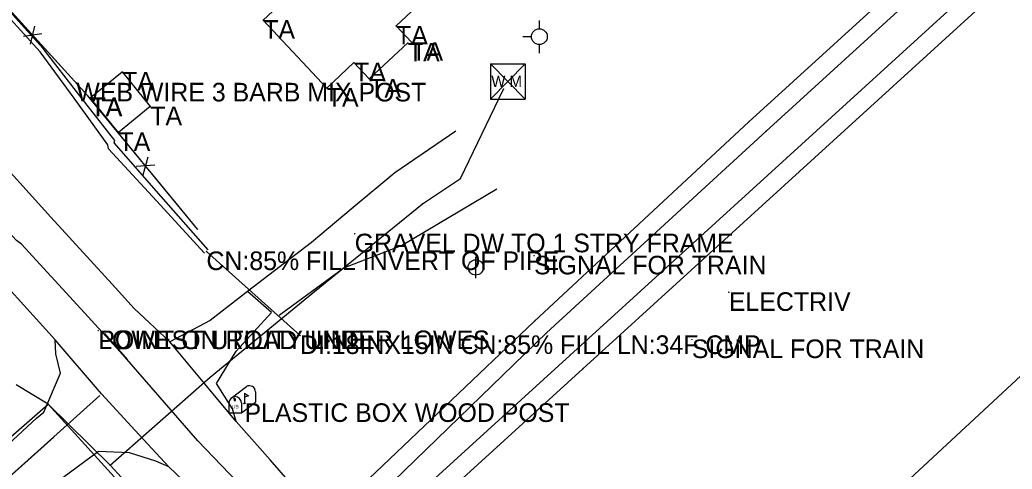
# Model space of a CAD drawing. Extents: x 1660112 to 1662239, y 668919 to 671377.
# Drawn here: x 1661444.9 to 1661711.4, y 670014.9 to 670135.7 of the extents above; entities that cross this region are included whole.
import ezdxf

# ---------------------------------------------------------------- set-up
doc = ezdxf.new("R2010")
doc.units = 0
for name, color, linetype in [('S_BUILDING', 7, 'Continuous'), ('S_BUILDING_ANNOT', 7, 'Continuous'), ('S_DITCHLINE', 7, 'Continuous'), ('S_DRG_PT_SYM', 7, 'Continuous'), ('S_DRIVEWAY', 7, 'Continuous'), ('S_EDGE_PAVEMENT', 7, 'Continuous'), ('S_ELECTRIC_UTILITIES_ANNOT', 7, 'Continuous'), ('S_FENCE', 7, 'Continuous'), ('S_FIBER_OPTIC_CABLE', 7, 'Continuous'), ('S_MAILBOX', 7, 'Continuous'), ('S_MAILBOX_ANNOT', 7, 'Continuous'), ('S_MISC_STRUCTURES_ANNOT', 7, 'Continuous'), ('S_MSC_PT_SYM', 7, 'Continuous'), ('S_PAVEMENT_CROWN', 7, 'Continuous'), ('S_RAILROAD', 7, 'Continuous'), ('S_SIDE_DRAIN', 7, 'Continuous'), ('S_SIDE_DRAIN_ANNOT', 7, 'Continuous'), ('S_STR_PT_SYM', 7, 'Continuous'), ('S_SURVEY_TEXT_ANNOT', 7, 'Continuous'), ('S_UTILITY_POLE', 7, 'Continuous'), ('S_UTL_PT_SYM', 7, 'Continuous'), ('S_WATER_UTILITIES', 7, 'Continuous')]:
    doc.layers.add(name, color=color, linetype=linetype)

msp = doc.modelspace()

# ---------------------------------------------------------------- linework, layer by layer
at = {"layer": 'S_BUILDING'}
for p, q in [((1661510.29, 670135.6), (1661528.55, 670152.68)), ((1661558.38, 670145.66), (1661545.97, 670134.05)), ((1661527.37, 670117.34), (1661510.29, 670135.6)), ((1661545.97, 670134.05), (1661550.07, 670129.67)), ((1661538.77, 670119.79), (1661549.14, 670129.49)), ((1661534.67, 670124.17), (1661527.37, 670117.34)), ((1661538.77, 670119.79), (1661534.67, 670124.17)), ((1661463.92, 670114.81), (1661472.39, 670121.69)), ((1661472.39, 670121.69), (1661479.95, 670112.37)), ((1661471.42, 670105.43), (1661463.85, 670114.75)), ((1661479.95, 670112.37), (1661471.42, 670105.43))]:
    msp.add_line(p, q, dxfattribs=at)
at = {"layer": 'S_DITCHLINE'}
for points in [[(1661494.51, 670072.98), (1661481.63, 670087.01), (1661468.75, 670101.04), (1661468.56, 670102.05), (1661459.49, 670114.59), (1661450.42, 670127.12), (1661437.16, 670141.71), (1661423.9, 670156.29), (1661409.97, 670171.2), (1661396.04, 670186.11), (1661384.96, 670198.23), (1661373.87, 670210.36), (1661354.32, 670219.23), (1661344.06, 670230.9), (1661333.8, 670242.57), (1661320.4, 670253.01)], [(1661495.46, 670073.89), (1661482.85, 670088.25), (1661470.25, 670102.6), (1661470.41, 670103.23), (1661460.8, 670115.6), (1661451.19, 670127.97), (1661437.9, 670142.65), (1661424.62, 670157.34), (1661411.2, 670172.34), (1661397.77, 670187.35), (1661386.72, 670199.36), (1661375.66, 670211.37), (1661356.56, 670219.75), (1661346.24, 670231.99), (1661335.91, 670244.22), (1661322, 670253.4)]]:
    msp.add_lwpolyline(points, dxfattribs=at)
at = {"layer": 'S_DRG_PT_SYM'}
for points in [[(1661495.04, 670073.44), (1661495.04, 670073.49), (1661495.04, 670073.44), (1661494.99, 670073.44), (1661495.04, 670073.44), (1661495.04, 670073.39), (1661495.04, 670073.44), (1661495.09, 670073.44)], [(1661520.17, 670050.89), (1661520.17, 670050.94), (1661520.17, 670050.89), (1661520.12, 670050.89), (1661520.17, 670050.89), (1661520.17, 670050.84), (1661520.17, 670050.89), (1661520.22, 670050.89)]]:
    msp.add_lwpolyline(points, dxfattribs=at)
at = {"layer": 'S_DRIVEWAY'}
for points in [[(1661562.01, 670105.73), (1661545.63, 670094.57), (1661534.43, 670085.23), (1661523.23, 670075.89)], [(1661514.57, 670056.35), (1661531.92, 670069.08), (1661547.4, 670075), (1661560.23, 670082.64), (1661573.05, 670090.29)], [(1661523.23, 670075.89), (1661506.06, 670062.67)]]:
    msp.add_lwpolyline(points, dxfattribs=at)
at = {"layer": 'S_EDGE_PAVEMENT'}
for points in [[(1661528.89, 670006.64), (1661525.81, 670010.93), (1661521.19, 670007.06), (1661512.12, 670017.42), (1661503.06, 670027.78), (1661494.14, 670038.45), (1661485.22, 670049.12), (1661475.65, 670058.13), (1661469.7, 670064.69), (1661453.26, 670082.63), (1661441.58, 670095.54), (1661429.9, 670108.45), (1661415.33, 670123.89), (1661400.76, 670139.32), (1661387.62, 670152.61), (1661374.47, 670165.9), (1661358.81, 670181.9), (1661343.14, 670197.9), (1661339.48, 670201.44), (1661329.75, 670211.05), (1661320.02, 670220.65), (1661304.77, 670236.19)], [(1661507.57, 669985.17), (1661503.63, 669990.55), (1661503.83, 669996.41), (1661492.59, 670008.33), (1661484.98, 670015.56), (1661475.91, 670025.37), (1661466.84, 670035.18), (1661454.4, 670049.73), (1661445.95, 670059), (1661437.51, 670068.28), (1661425.39, 670081.13), (1661413.28, 670093.99), (1661399.68, 670108.94), (1661386.08, 670123.89), (1661373.13, 670137.66), (1661360.18, 670151.43), (1661345.14, 670167.24), (1661330.11, 670183.04), (1661325.69, 670187.24), (1661316.74, 670196.41), (1661307.8, 670205.57), (1661291.28, 670222.16)], [(1661503.05, 670027.79), (1661502.07, 670031.11), (1661497.77, 670038), (1661503.02, 670046.62), (1661512.53, 670057.02), (1661506.06, 670062.67), (1661496.03, 670054.89), (1661485.23, 670049.11)], [(1661249.19, 669845.77), (1661252.39, 669848.76), (1661268.86, 669863.99), (1661278.76, 669872.97), (1661288.66, 669881.95), (1661300.04, 669892.31), (1661311.42, 669902.66), (1661327.02, 669916.7), (1661339.16, 669927.65), (1661351.29, 669938.61), (1661369.17, 669954.79), (1661387.06, 669970.96), (1661398.2, 669981.35), (1661409.34, 669991.75), (1661421.08, 670002.53), (1661432.82, 670013.32), (1661449.38, 670028.66), (1661451.32, 670030.24), (1661455.87, 670040.73), (1661454.57, 670045.91), (1661454.4, 670049.73)], [(1661484.97, 670015.57), (1661481.44, 670017.1), (1661474.37, 670019.33), (1661466.03, 670019.66), (1661456.43, 670012.6), (1661444.31, 670002.59), (1661432.19, 669992.58), (1661429.76, 669993.52), (1661418.03, 669982.83), (1661399.88, 669965.82), (1661383.18, 669950.54), (1661366.48, 669935.26), (1661355.84, 669925.69), (1661345.19, 669916.12), (1661334.54, 669906.55), (1661323.9, 669896.98), (1661314.39, 669888.26), (1661304.88, 669879.54), (1661295.37, 669870.82), (1661285.87, 669862.1), (1661271.87, 669849.3), (1661257.87, 669836.51)]]:
    msp.add_lwpolyline(points, dxfattribs=at)
at = {"layer": 'S_FENCE'}
for p, q in [((1661463.18, 670115.3), (1661437.44, 670143.55)), ((1661450.84, 670131.88), (1661445.88, 670131.24)), ((1661450.84, 670131.88), (1661445.88, 670131.24)), ((1661447.81, 670129.12), (1661448.91, 670134)), ((1661447.81, 670129.12), (1661448.91, 670134)), ((1661492.66, 670079.47), (1661463.18, 670115.3)), ((1661478.02, 670094.04), (1661479.36, 670098.86)), ((1661478.02, 670094.04), (1661479.36, 670098.86)), ((1661481.18, 670096.65), (1661476.2, 670096.26)), ((1661481.18, 670096.65), (1661476.2, 670096.26))]:
    msp.add_line(p, q, dxfattribs=at)
for points in [[(1661447.01, 670133.04), (1661437.44, 670143.55)], [(1661447.01, 670133.04), (1661437.44, 670143.55)], [(1661463.18, 670115.3), (1661449.7, 670130.09)], [(1661463.18, 670115.3), (1661449.7, 670130.09)], [(1661477.42, 670097.99), (1661463.18, 670115.3)], [(1661477.42, 670097.99), (1661463.18, 670115.3)], [(1661492.66, 670079.47), (1661479.96, 670094.91)], [(1661492.66, 670079.47), (1661479.96, 670094.91)]]:
    msp.add_lwpolyline(points, dxfattribs=at)
at = {"layer": 'S_FIBER_OPTIC_CABLE'}
msp.add_line((1661647.72, 669978.74), (1661720.75, 670046.56), dxfattribs=at)
at = {"layer": 'S_MAILBOX'}
for p, q in [((1661501.64, 670034.05), (1661505.78, 670037.16)), ((1661508.21, 670035.69), (1661508.21, 670032.97)), ((1661505.26, 670035.34), (1661505.26, 670032.63)), ((1661501.09, 670032.78), (1661501.09, 670030.06)), ((1661504.42, 670030.06), (1661508.21, 670032.97)), ((1661504.42, 670032.78), (1661504.42, 670030.06)), ((1661501.09, 670030.06), (1661504.42, 670030.06))]:
    msp.add_line(p, q, dxfattribs=at)
for points in [[(1661502.28, 670033.89), (1661502.5, 670033.76), (1661502.5, 670033.37), (1661502.8, 670033.37), (1661502.8, 670033.73), (1661502.61, 670033.98), (1661502.28, 670033.92)], [(1661505.26, 670035.34), (1661506.37, 670034.68), (1661505.26, 670034.33)]]:
    msp.add_lwpolyline(points, dxfattribs=at)
for centre, end in [((1661506.55, 670035.69), 117.5718), ((1661502.75, 670032.78), 180)]:
    msp.add_arc(centre, 1.66, 0, end, dxfattribs=at)
msp.add_ellipse((1661505.26, 670032.63), major_axis=(0.145, 0.132), ratio=0.564646, dxfattribs=at)
at = {"layer": 'S_MSC_PT_SYM'}
for points in [[(1661460.09, 670118.75), (1661460.09, 670118.8), (1661460.09, 670118.75), (1661460.04, 670118.75), (1661460.09, 670118.75), (1661460.09, 670118.7), (1661460.09, 670118.75), (1661460.14, 670118.75)], [(1661463.18, 670115.3), (1661463.18, 670115.35), (1661463.18, 670115.3), (1661463.13, 670115.3), (1661463.18, 670115.3), (1661463.18, 670115.25), (1661463.18, 670115.3), (1661463.23, 670115.3)], [(1661640.76, 670108.31), (1661640.76, 670108.36), (1661640.76, 670108.31), (1661640.71, 670108.31), (1661640.76, 670108.31), (1661640.76, 670108.26), (1661640.76, 670108.31), (1661640.81, 670108.31)], [(1661645.35, 670105.76), (1661645.35, 670105.81), (1661645.35, 670105.76), (1661645.3, 670105.76), (1661645.35, 670105.76), (1661645.35, 670105.71), (1661645.35, 670105.76), (1661645.4, 670105.76)], [(1661650.81, 670098.53), (1661650.81, 670098.58), (1661650.81, 670098.53), (1661650.76, 670098.53), (1661650.81, 670098.53), (1661650.81, 670098.48), (1661650.81, 670098.53), (1661650.86, 670098.53)], [(1661654.29, 670094.94), (1661654.29, 670094.99), (1661654.29, 670094.94), (1661654.24, 670094.94), (1661654.29, 670094.94), (1661654.29, 670094.89), (1661654.29, 670094.94), (1661654.34, 670094.94)], [(1661492.66, 670079.47), (1661492.66, 670079.52), (1661492.66, 670079.47), (1661492.61, 670079.47), (1661492.66, 670079.47), (1661492.66, 670079.42), (1661492.66, 670079.47), (1661492.71, 670079.47)], [(1661534.87, 670078.21), (1661534.87, 670078.26), (1661534.87, 670078.21), (1661534.82, 670078.21), (1661534.87, 670078.21), (1661534.87, 670078.16), (1661534.87, 670078.21), (1661534.92, 670078.21)], [(1661583.04, 670072.28), (1661583.04, 670072.33), (1661583.04, 670072.28), (1661582.99, 670072.28), (1661583.04, 670072.28), (1661583.04, 670072.23), (1661583.04, 670072.28), (1661583.09, 670072.28)], [(1661635.35, 670062.47), (1661635.35, 670062.52), (1661635.35, 670062.47), (1661635.3, 670062.47), (1661635.35, 670062.47), (1661635.35, 670062.42), (1661635.35, 670062.47), (1661635.4, 670062.47)], [(1661583.12, 670054.69), (1661583.12, 670054.74), (1661583.12, 670054.69), (1661583.07, 670054.69), (1661583.12, 670054.69), (1661583.12, 670054.64), (1661583.12, 670054.69), (1661583.17, 670054.69)], [(1661465.98, 670052.19), (1661465.98, 670052.24), (1661465.98, 670052.19), (1661465.93, 670052.19), (1661465.98, 670052.19), (1661465.98, 670052.14), (1661465.98, 670052.19), (1661466.03, 670052.19)], [(1661586.39, 670051.53), (1661586.39, 670051.58), (1661586.39, 670051.53), (1661586.34, 670051.53), (1661586.39, 670051.53), (1661586.39, 670051.48), (1661586.39, 670051.53), (1661586.44, 670051.53)], [(1661625.42, 670049.79), (1661625.42, 670049.84), (1661625.42, 670049.79), (1661625.37, 670049.79), (1661625.42, 670049.79), (1661625.42, 670049.74), (1661625.42, 670049.79), (1661625.47, 670049.79)], [(1661592.63, 670045.46), (1661592.63, 670045.51), (1661592.63, 670045.46), (1661592.58, 670045.46), (1661592.63, 670045.46), (1661592.63, 670045.41), (1661592.63, 670045.46), (1661592.68, 670045.46)], [(1661596.12, 670041.9), (1661596.12, 670041.95), (1661596.12, 670041.9), (1661596.07, 670041.9), (1661596.12, 670041.9), (1661596.12, 670041.85), (1661596.12, 670041.9), (1661596.17, 670041.9)]]:
    msp.add_lwpolyline(points, dxfattribs=at)
at = {"layer": 'S_PAVEMENT_CROWN'}
for points in [[(1661518.06, 669996.03), (1661505.4, 670009.31), (1661492.74, 670022.59), (1661480.19, 670036.99), (1661467.64, 670051.39), (1661473.76, 670044.39), (1661461.34, 670057.98), (1661445.4, 670075.38), (1661443.99, 670076.39), (1661432.69, 670088.65), (1661421.39, 670100.9), (1661407.48, 670115.88), (1661393.57, 670130.85), (1661380.41, 670144.59), (1661367.25, 670158.33), (1661351.88, 670174.26), (1661336.51, 670190.18), (1661332.38, 670194.36), (1661323.21, 670203.51), (1661314.05, 670212.66), (1661297.56, 670228.68)], [(1661253.85, 669840.46), (1661263.61, 669849.85), (1661273.37, 669859.23), (1661283.14, 669868.61), (1661292.9, 669878), (1661304.03, 669887.93), (1661315.16, 669897.86), (1661325.53, 669906.87), (1661335.91, 669915.88), (1661346.29, 669924.88), (1661356.66, 669933.89), (1661373.78, 669949.99), (1661390.9, 669966.09), (1661402.21, 669976.63), (1661413.52, 669987.17), (1661425.13, 669997.67), (1661436.73, 670008.16), (1661454.08, 670023.57), (1661444.42, 670014.94), (1661434.75, 670006.32), (1661450.56, 670020.53), (1661466.37, 670034.74)]]:
    msp.add_lwpolyline(points, dxfattribs=at)
at = {"layer": 'S_RAILROAD'}
for p, q in [((1661640.76, 670108.31), (1661697.88, 670160.33)), ((1661645.35, 670105.76), (1661700.23, 670155.87)), ((1661650.81, 670098.53), (1661707.23, 670149.96)), ((1661654.29, 670094.94), (1661710.74, 670146.35)), ((1661583.12, 670054.69), (1661640.76, 670108.31)), ((1661586.39, 670051.53), (1661645.35, 670105.76)), ((1661592.63, 670045.46), (1661650.81, 670098.53)), ((1661596.12, 670041.9), (1661654.29, 670094.94)), ((1661530.69, 670004.84), (1661583.12, 670054.69)), ((1661534.31, 670001.1), (1661586.39, 670051.53)), ((1661538.56, 669996.25), (1661592.63, 670045.46)), ((1661541.88, 669992.49), (1661596.12, 670041.9))]:
    msp.add_line(p, q, dxfattribs=at)
at = {"layer": 'S_SIDE_DRAIN'}
msp.add_line((1661520.17, 670050.89), (1661495.04, 670073.44), dxfattribs=at)
at = {"layer": 'S_STR_PT_SYM'}
for points in [[(1661510.29, 670135.6), (1661510.29, 670135.65), (1661510.29, 670135.6), (1661510.24, 670135.6), (1661510.29, 670135.6), (1661510.29, 670135.55), (1661510.29, 670135.6), (1661510.34, 670135.6)], [(1661545.97, 670134.05), (1661545.97, 670134.1), (1661545.97, 670134.05), (1661545.92, 670134.05), (1661545.97, 670134.05), (1661545.97, 670134), (1661545.97, 670134.05), (1661546.02, 670134.05)], [(1661549.14, 670129.49), (1661549.14, 670129.54), (1661549.14, 670129.49), (1661549.09, 670129.49), (1661549.14, 670129.49), (1661549.14, 670129.44), (1661549.14, 670129.49), (1661549.19, 670129.49)], [(1661550.07, 670129.67), (1661550.07, 670129.72), (1661550.07, 670129.67), (1661550.02, 670129.67), (1661550.07, 670129.67), (1661550.07, 670129.62), (1661550.07, 670129.67), (1661550.12, 670129.67)], [(1661534.67, 670124.17), (1661534.67, 670124.22), (1661534.67, 670124.17), (1661534.62, 670124.17), (1661534.67, 670124.17), (1661534.67, 670124.12), (1661534.67, 670124.17), (1661534.72, 670124.17)], [(1661472.39, 670121.69), (1661472.39, 670121.74), (1661472.39, 670121.69), (1661472.34, 670121.69), (1661472.39, 670121.69), (1661472.39, 670121.64), (1661472.39, 670121.69), (1661472.44, 670121.69)], [(1661538.77, 670119.79), (1661538.77, 670119.84), (1661538.77, 670119.79), (1661538.72, 670119.79), (1661538.77, 670119.79), (1661538.77, 670119.74), (1661538.77, 670119.79), (1661538.82, 670119.79)], [(1661527.37, 670117.34), (1661527.37, 670117.39), (1661527.37, 670117.34), (1661527.32, 670117.34), (1661527.37, 670117.34), (1661527.37, 670117.29), (1661527.37, 670117.34), (1661527.42, 670117.34)], [(1661463.85, 670114.75), (1661463.85, 670114.8), (1661463.85, 670114.75), (1661463.8, 670114.75), (1661463.85, 670114.75), (1661463.85, 670114.7), (1661463.85, 670114.75), (1661463.9, 670114.75)], [(1661463.92, 670114.81), (1661463.92, 670114.86), (1661463.92, 670114.81), (1661463.87, 670114.81), (1661463.92, 670114.81), (1661463.92, 670114.76), (1661463.92, 670114.81), (1661463.97, 670114.81)], [(1661479.95, 670112.37), (1661479.95, 670112.42), (1661479.95, 670112.37), (1661479.9, 670112.37), (1661479.95, 670112.37), (1661479.95, 670112.32), (1661479.95, 670112.37), (1661480, 670112.37)], [(1661471.42, 670105.43), (1661471.42, 670105.48), (1661471.42, 670105.43), (1661471.37, 670105.43), (1661471.42, 670105.43), (1661471.42, 670105.38), (1661471.42, 670105.43), (1661471.47, 670105.43)]]:
    msp.add_lwpolyline(points, dxfattribs=at)
at = {"layer": 'S_UTILITY_POLE'}
for p, q in [((1661584.45, 670133.26), (1661584.45, 670135.51)), ((1661582.36, 670131.13), (1661580.04, 670131.13)), ((1661584.53, 670126.71), (1661584.53, 670129.03)), ((1661567.37, 670066.23), (1661567.37, 670072.02))]:
    msp.add_line(p, q, dxfattribs=at)
for centre, radius in [((1661584.46, 670131.15), 2.13), ((1661567.37, 670069.16), 2.05)]:
    msp.add_circle(centre, radius, dxfattribs=at)
at = {"layer": 'S_UTL_PT_SYM'}
for points in [[(1661574.82, 670117.05), (1661574.82, 670117.1), (1661574.82, 670117.05), (1661574.77, 670117.05), (1661574.82, 670117.05), (1661574.82, 670117), (1661574.82, 670117.05), (1661574.87, 670117.05)], [(1661563.25, 670093.05), (1661563.25, 670093.1), (1661563.25, 670093.05), (1661563.2, 670093.05), (1661563.25, 670093.05), (1661563.25, 670093), (1661563.25, 670093.05), (1661563.3, 670093.05)], [(1661553.05, 670086.28), (1661553.05, 670086.33), (1661553.05, 670086.28), (1661553, 670086.28), (1661553.05, 670086.28), (1661553.05, 670086.23), (1661553.05, 670086.28), (1661553.1, 670086.28)], [(1661524.05, 670062.71), (1661524.05, 670062.76), (1661524.05, 670062.71), (1661524, 670062.71), (1661524.05, 670062.71), (1661524.05, 670062.66), (1661524.05, 670062.71), (1661524.1, 670062.71)], [(1661465.98, 670052.19), (1661465.98, 670052.24), (1661465.98, 670052.19), (1661465.93, 670052.19), (1661465.98, 670052.19), (1661465.98, 670052.14), (1661465.98, 670052.19), (1661466.03, 670052.19)], [(1661496.05, 670039.65), (1661496.05, 670039.7), (1661496.05, 670039.65), (1661496, 670039.65), (1661496.05, 670039.65), (1661496.05, 670039.6), (1661496.05, 670039.65), (1661496.1, 670039.65)], [(1661452.54, 670032.42), (1661452.54, 670032.47), (1661452.54, 670032.42), (1661452.49, 670032.42), (1661452.54, 670032.42), (1661452.54, 670032.37), (1661452.54, 670032.42), (1661452.59, 670032.42)], [(1661452.55, 670032.39), (1661452.55, 670032.44), (1661452.55, 670032.39), (1661452.5, 670032.39), (1661452.55, 670032.39), (1661452.55, 670032.34), (1661452.55, 670032.39), (1661452.6, 670032.39)], [(1661469.14, 670015.99), (1661469.14, 670016.04), (1661469.14, 670015.99), (1661469.09, 670015.99), (1661469.14, 670015.99), (1661469.14, 670015.94), (1661469.14, 670015.99), (1661469.19, 670015.99)], [(1661469.14, 670015.98), (1661469.14, 670016.03), (1661469.14, 670015.98), (1661469.09, 670015.98), (1661469.14, 670015.98), (1661469.14, 670015.93), (1661469.14, 670015.98), (1661469.19, 670015.98)]]:
    msp.add_lwpolyline(points, dxfattribs=at)
at = {"layer": 'S_WATER_UTILITIES'}
for p, q in [((1661571.34, 670123.87), (1661580.68, 670123.87)), ((1661571.34, 670123.87), (1661571.34, 670114.38)), ((1661571.34, 670123.87), (1661580.68, 670114.38)), ((1661580.68, 670123.87), (1661571.34, 670114.38)), ((1661580.68, 670123.87), (1661580.68, 670114.38)), ((1661563.25, 670093.05), (1661574.82, 670117.05)), ((1661571.34, 670114.38), (1661580.68, 670114.38)), ((1661553.05, 670086.28), (1661563.25, 670093.05)), ((1661524.05, 670062.71), (1661553.05, 670086.28)), ((1661496.05, 670039.65), (1661524.05, 670062.71)), ((1661469.14, 670015.99), (1661496.05, 670039.65)), ((1661452.55, 670032.39), (1661443.91, 670037.56)), ((1661408.52, 669993.88), (1661452.54, 670032.42)), ((1661528.82, 669948.66), (1661452.55, 670032.39)), ((1661452.55, 670032.39), (1661469.14, 670015.98)), ((1661472.2, 670012.7), (1661469.14, 670015.98))]:
    msp.add_line(p, q, dxfattribs=at)

# ---------------------------------------------------------------- texts
at = {"layer": 'S_BUILDING_ANNOT'}
for p in [(1661510.29, 670130.6), (1661545.97, 670129.05), (1661549.14, 670124.49), (1661550.07, 670124.67), (1661534.67, 670119.17), (1661472.39, 670116.69), (1661538.77, 670114.79), (1661527.37, 670112.34), (1661463.85, 670109.75), (1661463.92, 670109.81), (1661479.95, 670107.37), (1661471.42, 670100.43)]:
    msp.add_text('TA', height=5, dxfattribs=at).set_placement(p)
at = {"layer": 'S_ELECTRIC_UTILITIES_ANNOT'}
msp.add_text('LOWEST UTILITY LINE', height=5, dxfattribs=at).set_placement((1661465.98, 670047.19))
at = {"layer": 'S_MAILBOX'}
msp.add_text('US', height=0.96, rotation=360, dxfattribs=at).set_placement((1661501.85, 670031.26))
at = {"layer": 'S_MAILBOX_ANNOT'}
msp.add_text('PLASTIC BOX WOOD POST', height=5, dxfattribs=at).set_placement((1661505.26, 670027.63))
at = {"layer": 'S_MISC_STRUCTURES_ANNOT'}
for s, p in [('SIGNAL FOR TRAIN', (1661583.04, 670067.28)), ('ELECTRIV', (1661635.35, 670057.47)), ('SIGNAL FOR TRAIN', (1661625.42, 670044.79))]:
    msp.add_text(s, height=5, dxfattribs=at).set_placement(p)
at = {"layer": 'S_SIDE_DRAIN_ANNOT'}
for s, p in [('CN:85% FILL INVERT OF PIPE', (1661495.04, 670068.44)), ('DI:18INX15IN CN:85% FILL LN:34F CMP', (1661520.17, 670045.89))]:
    msp.add_text(s, height=5, dxfattribs=at).set_placement(p)
at = {"layer": 'S_SURVEY_TEXT_ANNOT'}
for s, p in [('WEB WIRE 3 BARB MIX POST', (1661460.09, 670113.75)), ('GRAVEL DW TO 1 STRY FRAME', (1661534.87, 670073.21)), ('POINT ON ROAD UNDER LOWES', (1661465.98, 670047.19))]:
    msp.add_text(s, height=5, dxfattribs=at).set_placement(p)
at = {"layer": 'S_WATER_UTILITIES'}
msp.add_text('W M', height=3, rotation=360, dxfattribs=at).set_placement((1661571.55, 670117.64))

doc.saveas('drawing.dxf')
